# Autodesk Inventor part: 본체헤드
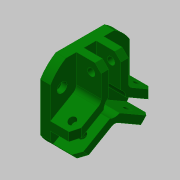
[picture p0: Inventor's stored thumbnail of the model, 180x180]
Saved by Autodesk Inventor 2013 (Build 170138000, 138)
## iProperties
Created: 2020-02
Part Number: 본체헤드
Material: 알루미늄 6061
Document SubType Name: Modeling
Designer: mduedu
Density: 1 g/cm^3
Author: mduedu
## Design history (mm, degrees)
sketch "스케치1"
  geometry: L1 (-32, -32)-(32, -32); L2 (32, -32)-(32, 32); L3 (32, 32)-(-32, 32); L4 (-32, 32)-(-32, -32); L5 (-32, -32)-(32, 32); L6 (32, -32)-(-32, 32); 1 further point
  constraints: 12 end point, 2 midpoint, 2 parallel, 1 horizontal, 1 perpendicular
  dimensions: "d0" = 64 distance of L3.end L2.end; "d1" = 64 distance of L2.end L1.end
extrude "돌출1" new body sketch "스케치1" distance "d2" = 28; taper "d3" = 0 deg
sketch "스케치2"
  geometry: C1 r 37.5 at (0, 0); 1 further point
  constraints: 1 centre point, 1 coincident
  dimensions: "d4" = 75 diameter of C1
extrude "돌출2" sketch "스케치2" stored distance "d5" = 28; taper "d6" = 0 deg
sketch "스케치3"
  geometry: C1 r 20 at (0, 0); 1 further point
  constraints: 1 centre point, 1 coincident
  dimensions: "d7" = 40 diameter of C1
extrude "돌출3" join sketch "스케치3" distance "d8" = 12; taper "d9" = 0 deg
sketch "스케치4"
  geometry: L1 (-32, 19.551)-(-32, -19.551) reference; L2 (-19.551, -32)-(19.551, -32) reference; L3 (32, -19.551)-(32, 19.551) reference; L4 (19.551, 32)-(-19.551, 32) reference; L5 (0, 0)-(0, 37.5); L6 (0, 0)-(32.476, -18.75); L7 (0, 0)-(-32.476, -18.75); L8 (11, 6.351)-(11, 35.85); L9 (-11, 6.351)-(-11, 35.85); L10 (-11, 6.351)-(-36.547, -8.399); L11 (0, -12.702)-(-25.547, -27.451); L12 (11, 6.351)-(36.547, -8.399); L13 (0, -12.702)-(25.547, -27.451); L14 (-5, 2.887)-(-5, 37.165); L15 (5, 2.887)-(5, 37.165); L16 (-5, 2.887)-(-34.686, -14.252); L17 (0, -5.774)-(-29.686, -22.913); L18 (0, -5.774)-(29.686, -22.913); L19 (5, 2.887)-(34.686, -14.252); A1 r 37.5 centre (0, 0) between (-19.551, 32) and (-32, 19.551) reference; A2 r 37.5 centre (0, 0) between (-32, -19.551) and (-19.551, -32) reference; A3 r 37.5 centre (0, 0) between (19.551, -32) and (32, -19.551) reference; A4 r 37.5 centre (0, 0) between (32, 19.551) and (19.551, 32) reference; 1 further point
  constraints: 30 end point, 12 parallel, 2 point on circle, 1 coincident, 1 perpendicular, 24 other
  dimensions: "d10" = 120 deg angle of L6 L5; "d11" = 120 deg angle of L7 L6; "d12" = 22 distance between parallel lines of L8 L9; "d14" = 22 distance between parallel lines of L11 L10; "d15" = 22 distance between parallel lines of L12 L13; "d18" = 10 distance between parallel lines of L15 L14; "d19" = 10 distance between parallel lines of L18 L19; "d20" = 10 distance between parallel lines of L16 L17
  node "투영된 루프1"
extrude "돌출4" cut sketch "스케치4" distance "d16" = 20; taper "d17" = 0 deg
extrude "돌출5" cut sketch "스케치4" distance "d21" = 20; taper "d22" = 0 deg
sketch "스케치5"
  geometry: C1 r 9 at (0, 0); 1 further point
  constraints: 1 centre point, 1 coincident
  dimensions: "d23" = 18 diameter of C1
extrude "돌출6" cut sketch "스케치5" stored distance "d24" = 20; taper "d25" = 0 deg
sketch "스케치6"
  geometry: L1 (32, 0)-(19.551, 0) reference; C1 r 3 at (24, 20); 1 further point
  constraints: 1 centre point
  dimensions: "d26" = 6 diameter of C1; "d27" = 24 horizontal distance of C1.centre point (0, 0); "d28" = 20 distance from line of C1.centre L1
extrude "돌출7" cut sketch "스케치6" stored distance "d29" = 20; taper "d30" = 0 deg
sketch "스케치7"
  geometry: L1 (-20, -12)-(-20, 0) reference; L2 (-20, 0)-(-32, 0) reference; L3 (-32, 0)-(-32, 8) reference; L4 (-32, 8)-(-12.702, 8) reference; L5 (-12.702, 8)-(-12.702, 28) reference; L6 (-12.702, 28)-(-9, 28) reference; L7 (-9, 28)-(-9, -12) reference; L8 (-9, -12)-(-20, -12) reference; L9 (20, 0)-(20, -12) reference; L10 (20, -12)-(9, -12) reference; L11 (9, -12)-(9, 8) reference; L12 (9, 8)-(32, 8) reference; L13 (32, 8)-(32, 0) reference; L14 (32, 0)-(20, 0) reference; L15 (20, -8.35)-(17, -8.35); L16 (17, -8.35)-(17, -3.65); L17 (17, -3.65)-(20, -3.65); L18 (20, -3.65)-(20, -8.35); L19 (9, -2.4)-(11, -2.4); L20 (11, -2.4)-(11, -5.6); L21 (11, -5.6)-(9, -5.6); L22 (9, -5.6)-(9, -2.4); L23 (0, -20)-(0, 36) reference; L24 (17, -6)-(20, -6); L25 (11, -4)-(9, -4); 1 further point
  constraints: 20 end point, 4 midpoint, 4 parallel, 2 horizontal, 2 perpendicular, 2 point on line
  dimensions: "d34" = 6 distance between parallel lines of L24 L14; "d35" = 34 diameter of L16 L23; "d36" = 4.7 distance between parallel lines of L17 L15; "d37" = 8 distance between parallel lines of L25 L10; "d38" = 3.2 distance of L19.end L20.end; "d39" = 22 diameter of L20 L23
revolve "회전1" sketch "스케치7" stored, may be unused: angle "d40" = 90 deg
fillet "모깎기1" dims "d41" = 0.8
fillet "모깎기2" dims "d42" = 0.4
chamfer "모따기1" distance "d43" = 0.3; stored, may be unused: second distance "d44" = 2, angle "d45" = 45 deg
chamfer "모따기2" distance "d46" = 0.3; stored, may be unused: second distance "d47" = 2, angle "d48" = 45 deg
chamfer "모따기3" distance "d49" = 1; stored, may be unused: second distance "d50" = 2, angle "d51" = 45 deg
fillet "모깎기3" dims "d52" = 5
chamfer "모따기4" distance "d53" = 5; stored, may be unused: second distance "d54" = 2, angle "d55" = 45 deg
sketch "스케치8" dims "d56" = 52
  geometry: 3 further points
  constraints: 2 vertical alignment, 1 coincident, 2 other
hole "구멍1" sketch "스케치8" at (0, -26) diameter "d57" = 4.5; stored, may be unused: countersink angle "d61" = 90 deg, drill point angle "d63" = 118 deg; dims "d58" = 6, "d59" = 8, "d60" = 4.4, "d62" = 8
node "작업 평면1"
node "작업 평면2"
node "솔리드1"
pattern_circular "원형 패턴1" dims angle "d32" = 360 deg
pattern_circular "원형 패턴2" dims angle "d65" = 360 deg
node "절단 모서리 투영1"
